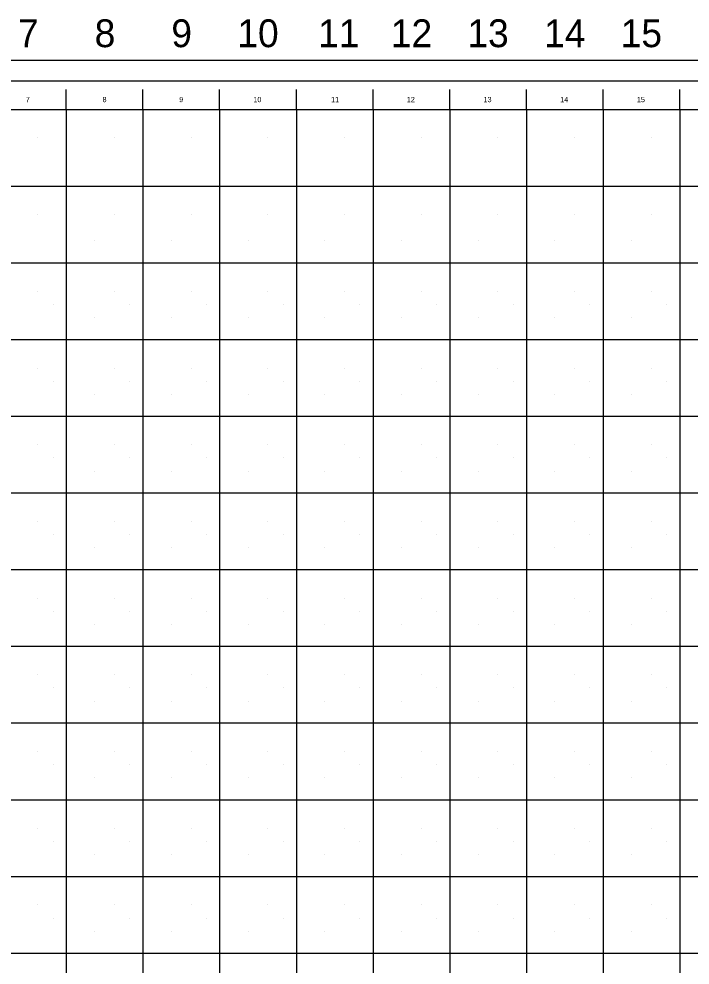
# Model space of a CAD drawing. Extents: x -0.05 to 1.19, y 0 to 0.86.
# Drawn here: x 0.2585 to 0.5647, y 0.428 to 0.8598 of the extents above; entities that cross this region are included whole.
import ezdxf

# ---------------------------------------------------------------- set-up
doc = ezdxf.new("R2010")
doc.units = 0
for name, color, linetype in [('G-ANNO-NPLT', 7, 'Continuous'), ('G-ANNO-TEXT', 7, 'Continuous'), ('G-ANNO-TTLB', 7, 'Continuous'), ('G-ANNO-TTLB-GRID', 7, 'Continuous')]:
    doc.layers.add(name, color=color, linetype=linetype)

msp = doc.modelspace()

# ---------------------------------------------------------------- linework, layer by layer
at = {"layer": 'G-ANNO-NPLT'}
for p, q in [((0.26708, 0.80547), (0.26708, 0.80547)), ((0.30207, 0.80547), (0.30207, 0.80547)), ((0.33707, 0.80547), (0.33707, 0.80547)), ((0.37207, 0.80547), (0.37207, 0.80547)), ((0.40707, 0.80547), (0.40707, 0.80547)), ((0.44207, 0.80547), (0.44207, 0.80547)), ((0.47707, 0.80547), (0.47707, 0.80547)), ((0.51207, 0.80547), (0.51207, 0.80547)), ((0.54707, 0.80547), (0.54707, 0.80547)), ((0.26708, 0.77047), (0.26708, 0.77047)), ((0.30207, 0.77047), (0.30207, 0.77047)), ((0.33707, 0.77047), (0.33707, 0.77047)), ((0.37207, 0.77047), (0.37207, 0.77047)), ((0.40707, 0.77047), (0.40707, 0.77047)), ((0.44207, 0.77047), (0.44207, 0.77047)), ((0.47707, 0.77047), (0.47707, 0.77047)), ((0.51207, 0.77047), (0.51207, 0.77047)), ((0.54707, 0.77047), (0.54707, 0.77047)), ((0.29307, 0.75847), (0.29307, 0.75847)), ((0.32808, 0.75847), (0.32808, 0.75847)), ((0.36307, 0.75847), (0.36307, 0.75847)), ((0.39807, 0.75847), (0.39807, 0.75847)), ((0.43307, 0.75847), (0.43307, 0.75847)), ((0.46807, 0.75847), (0.46807, 0.75847)), ((0.50307, 0.75847), (0.50307, 0.75847)), ((0.53807, 0.75847), (0.53807, 0.75847)), ((0.26708, 0.73547), (0.26708, 0.73547)), ((0.30207, 0.73547), (0.30207, 0.73547)), ((0.33707, 0.73547), (0.33707, 0.73547)), ((0.37207, 0.73547), (0.37207, 0.73547)), ((0.40707, 0.73547), (0.40707, 0.73547)), ((0.44207, 0.73547), (0.44207, 0.73547)), ((0.47707, 0.73547), (0.47707, 0.73547)), ((0.51207, 0.73547), (0.51207, 0.73547)), ((0.54707, 0.73547), (0.54707, 0.73547)), ((0.27408, 0.72947), (0.27408, 0.72947)), ((0.30907, 0.72947), (0.30907, 0.72947)), ((0.34407, 0.72947), (0.34407, 0.72947)), ((0.37907, 0.72947), (0.37907, 0.72947)), ((0.41407, 0.72947), (0.41407, 0.72947)), ((0.44908, 0.72947), (0.44908, 0.72947)), ((0.48407, 0.72947), (0.48407, 0.72947)), ((0.51907, 0.72947), (0.51907, 0.72947)), ((0.55407, 0.72947), (0.55407, 0.72947)), ((0.29307, 0.72347), (0.29307, 0.72347)), ((0.32808, 0.72347), (0.32808, 0.72347)), ((0.36307, 0.72347), (0.36307, 0.72347)), ((0.39807, 0.72347), (0.39807, 0.72347)), ((0.43307, 0.72347), (0.43307, 0.72347)), ((0.46807, 0.72347), (0.46807, 0.72347)), ((0.50307, 0.72347), (0.50307, 0.72347)), ((0.53807, 0.72347), (0.53807, 0.72347)), ((0.26708, 0.70047), (0.26708, 0.70047)), ((0.30207, 0.70047), (0.30207, 0.70047)), ((0.33707, 0.70047), (0.33707, 0.70047)), ((0.37207, 0.70047), (0.37207, 0.70047)), ((0.40707, 0.70047), (0.40707, 0.70047)), ((0.44207, 0.70047), (0.44207, 0.70047)), ((0.47707, 0.70047), (0.47707, 0.70047)), ((0.51207, 0.70047), (0.51207, 0.70047)), ((0.54707, 0.70047), (0.54707, 0.70047)), ((0.27408, 0.69447), (0.27408, 0.69447)), ((0.30907, 0.69447), (0.30907, 0.69447)), ((0.34407, 0.69447), (0.34407, 0.69447)), ((0.37907, 0.69447), (0.37907, 0.69447)), ((0.41407, 0.69447), (0.41407, 0.69447)), ((0.44908, 0.69447), (0.44908, 0.69447)), ((0.48407, 0.69447), (0.48407, 0.69447)), ((0.51907, 0.69447), (0.51907, 0.69447)), ((0.55407, 0.69447), (0.55407, 0.69447)), ((0.29307, 0.68847), (0.29307, 0.68847)), ((0.32808, 0.68847), (0.32808, 0.68847)), ((0.36307, 0.68847), (0.36307, 0.68847)), ((0.39807, 0.68847), (0.39807, 0.68847)), ((0.43307, 0.68847), (0.43307, 0.68847)), ((0.46807, 0.68847), (0.46807, 0.68847)), ((0.50307, 0.68847), (0.50307, 0.68847)), ((0.53807, 0.68847), (0.53807, 0.68847)), ((0.26708, 0.66547), (0.26708, 0.66547)), ((0.30207, 0.66547), (0.30207, 0.66547)), ((0.33707, 0.66547), (0.33707, 0.66547)), ((0.37207, 0.66547), (0.37207, 0.66547)), ((0.40707, 0.66547), (0.40707, 0.66547)), ((0.44207, 0.66547), (0.44207, 0.66547)), ((0.47707, 0.66547), (0.47707, 0.66547)), ((0.51207, 0.66547), (0.51207, 0.66547)), ((0.54707, 0.66547), (0.54707, 0.66547)), ((0.27408, 0.65947), (0.27408, 0.65947)), ((0.30907, 0.65947), (0.30907, 0.65947)), ((0.34407, 0.65947), (0.34407, 0.65947)), ((0.37907, 0.65947), (0.37907, 0.65947)), ((0.41407, 0.65947), (0.41407, 0.65947)), ((0.44908, 0.65947), (0.44908, 0.65947)), ((0.48407, 0.65947), (0.48407, 0.65947)), ((0.51907, 0.65947), (0.51907, 0.65947)), ((0.55407, 0.65947), (0.55407, 0.65947)), ((0.29307, 0.65347), (0.29307, 0.65347)), ((0.32808, 0.65347), (0.32808, 0.65347)), ((0.36307, 0.65347), (0.36307, 0.65347)), ((0.39807, 0.65347), (0.39807, 0.65347)), ((0.43307, 0.65347), (0.43307, 0.65347)), ((0.46807, 0.65347), (0.46807, 0.65347)), ((0.50307, 0.65347), (0.50307, 0.65347)), ((0.53807, 0.65347), (0.53807, 0.65347)), ((0.26708, 0.63047), (0.26708, 0.63047)), ((0.30207, 0.63047), (0.30207, 0.63047)), ((0.33707, 0.63047), (0.33707, 0.63047)), ((0.37207, 0.63047), (0.37207, 0.63047)), ((0.40707, 0.63047), (0.40707, 0.63047)), ((0.44207, 0.63047), (0.44207, 0.63047)), ((0.47707, 0.63047), (0.47707, 0.63047)), ((0.51207, 0.63047), (0.51207, 0.63047)), ((0.54707, 0.63047), (0.54707, 0.63047)), ((0.27408, 0.62447), (0.27408, 0.62447)), ((0.30907, 0.62447), (0.30907, 0.62447)), ((0.34407, 0.62447), (0.34407, 0.62447)), ((0.37907, 0.62447), (0.37907, 0.62447)), ((0.41407, 0.62447), (0.41407, 0.62447)), ((0.44908, 0.62447), (0.44908, 0.62447)), ((0.48407, 0.62447), (0.48407, 0.62447)), ((0.51907, 0.62447), (0.51907, 0.62447)), ((0.55407, 0.62447), (0.55407, 0.62447)), ((0.29307, 0.61847), (0.29307, 0.61847)), ((0.32808, 0.61847), (0.32808, 0.61847)), ((0.36307, 0.61847), (0.36307, 0.61847)), ((0.39807, 0.61847), (0.39807, 0.61847)), ((0.43307, 0.61847), (0.43307, 0.61847)), ((0.46807, 0.61847), (0.46807, 0.61847)), ((0.50307, 0.61847), (0.50307, 0.61847)), ((0.53807, 0.61847), (0.53807, 0.61847)), ((0.26708, 0.59547), (0.26708, 0.59547)), ((0.30207, 0.59547), (0.30207, 0.59547)), ((0.33707, 0.59547), (0.33707, 0.59547)), ((0.37207, 0.59547), (0.37207, 0.59547)), ((0.40707, 0.59547), (0.40707, 0.59547)), ((0.44207, 0.59547), (0.44207, 0.59547)), ((0.47707, 0.59547), (0.47707, 0.59547)), ((0.51207, 0.59547), (0.51207, 0.59547)), ((0.54707, 0.59547), (0.54707, 0.59547)), ((0.27408, 0.58947), (0.27408, 0.58947)), ((0.30907, 0.58947), (0.30907, 0.58947)), ((0.34407, 0.58947), (0.34407, 0.58947)), ((0.37907, 0.58947), (0.37907, 0.58947)), ((0.41407, 0.58947), (0.41407, 0.58947)), ((0.44908, 0.58947), (0.44908, 0.58947)), ((0.48407, 0.58947), (0.48407, 0.58947)), ((0.51907, 0.58947), (0.51907, 0.58947)), ((0.55407, 0.58947), (0.55407, 0.58947)), ((0.29307, 0.58347), (0.29307, 0.58347)), ((0.32808, 0.58347), (0.32808, 0.58347)), ((0.36307, 0.58347), (0.36307, 0.58347)), ((0.39807, 0.58347), (0.39807, 0.58347)), ((0.43307, 0.58347), (0.43307, 0.58347)), ((0.46807, 0.58347), (0.46807, 0.58347)), ((0.50307, 0.58347), (0.50307, 0.58347)), ((0.53807, 0.58347), (0.53807, 0.58347)), ((0.26708, 0.56047), (0.26708, 0.56047)), ((0.30207, 0.56047), (0.30207, 0.56047)), ((0.33707, 0.56047), (0.33707, 0.56047)), ((0.37207, 0.56047), (0.37207, 0.56047)), ((0.40707, 0.56047), (0.40707, 0.56047)), ((0.44207, 0.56047), (0.44207, 0.56047)), ((0.47707, 0.56047), (0.47707, 0.56047)), ((0.51207, 0.56047), (0.51207, 0.56047)), ((0.54707, 0.56047), (0.54707, 0.56047)), ((0.27408, 0.55447), (0.27408, 0.55447)), ((0.30907, 0.55447), (0.30907, 0.55447)), ((0.34407, 0.55447), (0.34407, 0.55447)), ((0.37907, 0.55447), (0.37907, 0.55447)), ((0.41407, 0.55447), (0.41407, 0.55447)), ((0.44908, 0.55447), (0.44908, 0.55447)), ((0.48407, 0.55447), (0.48407, 0.55447)), ((0.51907, 0.55447), (0.51907, 0.55447)), ((0.55407, 0.55447), (0.55407, 0.55447)), ((0.29307, 0.54847), (0.29307, 0.54847)), ((0.32808, 0.54847), (0.32808, 0.54847)), ((0.36307, 0.54847), (0.36307, 0.54847)), ((0.39807, 0.54847), (0.39807, 0.54847)), ((0.43307, 0.54847), (0.43307, 0.54847)), ((0.46807, 0.54847), (0.46807, 0.54847)), ((0.50307, 0.54847), (0.50307, 0.54847)), ((0.53807, 0.54847), (0.53807, 0.54847)), ((0.26708, 0.52547), (0.26708, 0.52547)), ((0.30207, 0.52547), (0.30207, 0.52547)), ((0.33707, 0.52547), (0.33707, 0.52547)), ((0.37207, 0.52547), (0.37207, 0.52547)), ((0.40707, 0.52547), (0.40707, 0.52547)), ((0.44207, 0.52547), (0.44207, 0.52547)), ((0.47707, 0.52547), (0.47707, 0.52547)), ((0.51207, 0.52547), (0.51207, 0.52547)), ((0.54707, 0.52547), (0.54707, 0.52547)), ((0.27408, 0.51947), (0.27408, 0.51947)), ((0.30907, 0.51947), (0.30907, 0.51947)), ((0.34407, 0.51947), (0.34407, 0.51947)), ((0.37907, 0.51947), (0.37907, 0.51947)), ((0.41407, 0.51947), (0.41407, 0.51947)), ((0.44908, 0.51947), (0.44908, 0.51947)), ((0.48407, 0.51947), (0.48407, 0.51947)), ((0.51907, 0.51947), (0.51907, 0.51947)), ((0.55407, 0.51947), (0.55407, 0.51947)), ((0.29307, 0.51347), (0.29307, 0.51347)), ((0.32808, 0.51347), (0.32808, 0.51347)), ((0.36307, 0.51347), (0.36307, 0.51347)), ((0.39807, 0.51347), (0.39807, 0.51347)), ((0.43307, 0.51347), (0.43307, 0.51347)), ((0.46807, 0.51347), (0.46807, 0.51347)), ((0.50307, 0.51347), (0.50307, 0.51347)), ((0.53807, 0.51347), (0.53807, 0.51347)), ((0.26708, 0.49047), (0.26708, 0.49047)), ((0.30207, 0.49047), (0.30207, 0.49047)), ((0.33707, 0.49047), (0.33707, 0.49047)), ((0.37207, 0.49047), (0.37207, 0.49047)), ((0.40707, 0.49047), (0.40707, 0.49047)), ((0.44207, 0.49047), (0.44207, 0.49047)), ((0.47707, 0.49047), (0.47707, 0.49047)), ((0.51207, 0.49047), (0.51207, 0.49047)), ((0.54707, 0.49047), (0.54707, 0.49047)), ((0.27408, 0.48447), (0.27408, 0.48447)), ((0.30907, 0.48447), (0.30907, 0.48447)), ((0.34407, 0.48447), (0.34407, 0.48447)), ((0.37907, 0.48447), (0.37907, 0.48447)), ((0.41407, 0.48447), (0.41407, 0.48447)), ((0.44908, 0.48447), (0.44908, 0.48447)), ((0.48407, 0.48447), (0.48407, 0.48447)), ((0.51907, 0.48447), (0.51907, 0.48447)), ((0.55407, 0.48447), (0.55407, 0.48447)), ((0.29307, 0.47847), (0.29307, 0.47847)), ((0.32808, 0.47847), (0.32808, 0.47847)), ((0.36307, 0.47847), (0.36307, 0.47847)), ((0.39807, 0.47847), (0.39807, 0.47847)), ((0.43307, 0.47847), (0.43307, 0.47847)), ((0.46807, 0.47847), (0.46807, 0.47847)), ((0.50307, 0.47847), (0.50307, 0.47847)), ((0.53807, 0.47847), (0.53807, 0.47847)), ((0.26708, 0.45547), (0.26708, 0.45547)), ((0.30207, 0.45547), (0.30207, 0.45547)), ((0.33707, 0.45547), (0.33707, 0.45547)), ((0.37207, 0.45547), (0.37207, 0.45547)), ((0.40707, 0.45547), (0.40707, 0.45547)), ((0.44207, 0.45547), (0.44207, 0.45547)), ((0.47707, 0.45547), (0.47707, 0.45547)), ((0.51207, 0.45547), (0.51207, 0.45547)), ((0.54707, 0.45547), (0.54707, 0.45547)), ((0.27408, 0.44947), (0.27408, 0.44947)), ((0.30907, 0.44947), (0.30907, 0.44947)), ((0.34407, 0.44947), (0.34407, 0.44947)), ((0.37907, 0.44947), (0.37907, 0.44947)), ((0.41407, 0.44947), (0.41407, 0.44947)), ((0.44908, 0.44947), (0.44908, 0.44947)), ((0.48407, 0.44947), (0.48407, 0.44947)), ((0.51907, 0.44947), (0.51907, 0.44947)), ((0.55407, 0.44947), (0.55407, 0.44947)), ((0.29307, 0.44347), (0.29307, 0.44347)), ((0.32808, 0.44347), (0.32808, 0.44347)), ((0.36307, 0.44347), (0.36307, 0.44347)), ((0.39807, 0.44347), (0.39807, 0.44347)), ((0.43307, 0.44347), (0.43307, 0.44347)), ((0.46807, 0.44347), (0.46807, 0.44347)), ((0.50307, 0.44347), (0.50307, 0.44347)), ((0.53807, 0.44347), (0.53807, 0.44347))]:
    msp.add_line(p, q, dxfattribs=at)
msp.add_lwpolyline([(0.00952, 0.83147), (1.17948, 0.83147), (1.17948, 0.00952), (0.00952, 0.00952)], close=True, dxfattribs=at)
at = {"layer": 'G-ANNO-TEXT'}
for p, q in [((0.28007, 0.81847), (0.28007, 0.82753)), ((0.31507, 0.81847), (0.31507, 0.82753)), ((0.35007, 0.81847), (0.35007, 0.82753)), ((0.38508, 0.81847), (0.38508, 0.82753)), ((0.42007, 0.81847), (0.42007, 0.82753)), ((0.45507, 0.81847), (0.45507, 0.82753)), ((0.49007, 0.81847), (0.49007, 0.82753)), ((0.52507, 0.81847), (0.52507, 0.82753)), ((0.56007, 0.81847), (0.56007, 0.82753))]:
    msp.add_line(p, q, dxfattribs=at)
at = {"layer": 'G-ANNO-TTLB'}
for points in [[(0, 0.841), (1.189, 0.841), (1.189, 0), (0, 0)], [(0.03507, 0.81847), (1.17009, 0.81847), (1.17009, 0.01347), (0.03507, 0.01347)]]:
    msp.add_lwpolyline(points, close=True, dxfattribs=at)
at = {"layer": 'G-ANNO-TTLB-GRID'}
for p, q in [((0.28007, 0.81847), (0.28007, 0.01347)), ((0.31507, 0.81847), (0.31507, 0.01347)), ((0.35007, 0.81847), (0.35007, 0.01347)), ((0.38508, 0.81847), (0.38508, 0.01347)), ((0.42007, 0.81847), (0.42007, 0.01347)), ((0.45507, 0.81847), (0.45507, 0.01347)), ((0.49007, 0.81847), (0.49007, 0.01347)), ((0.52507, 0.81847), (0.52507, 0.01347)), ((0.56007, 0.81847), (0.56007, 0.01347)), ((0.03507, 0.78347), (1.17009, 0.78347)), ((0.03507, 0.74847), (1.17009, 0.74847)), ((0.03507, 0.71347), (1.17009, 0.71347)), ((0.03507, 0.67847), (1.17009, 0.67847)), ((0.03507, 0.64347), (1.17009, 0.64347)), ((0.03507, 0.60847), (1.17009, 0.60847)), ((0.03507, 0.57347), (1.12007, 0.57347)), ((0.03507, 0.53847), (1.12007, 0.53847)), ((0.03507, 0.50347), (1.12007, 0.50347)), ((0.03507, 0.46847), (1.12007, 0.46847)), ((0.03507, 0.43347), (1.12007, 0.43347))]:
    msp.add_line(p, q, dxfattribs=at)

# ---------------------------------------------------------------- texts
at = {"layer": 'G-ANNO-NPLT'}
for s, p in [('7', (0.25804, 0.8469)), ('8', (0.29304, 0.8469)), ('9', (0.32804, 0.8469)), ('10', (0.35814, 0.8469)), ('11', (0.395, 0.8469)), ('12', (0.42818, 0.8469)), ('13', (0.46311, 0.8469)), ('14', (0.49814, 0.8469)), ('15', (0.53306, 0.8469))]:
    msp.add_text(s, height=0.0127, dxfattribs=at).set_placement(p)
at = {"layer": 'G-ANNO-TEXT'}
for s, p in [('7', (0.26163, 0.8218)), ('8', (0.29663, 0.8218)), ('9', (0.33163, 0.8218)), ('10', (0.36547, 0.8218)), ('11', (0.40091, 0.8218)), ('12', (0.43548, 0.8218)), ('13', (0.47047, 0.8218)), ('14', (0.50548, 0.8218)), ('15', (0.54046, 0.8218))]:
    msp.add_text(s, height=0.0024, dxfattribs=at).set_placement(p)

doc.saveas('drawing.dxf')
